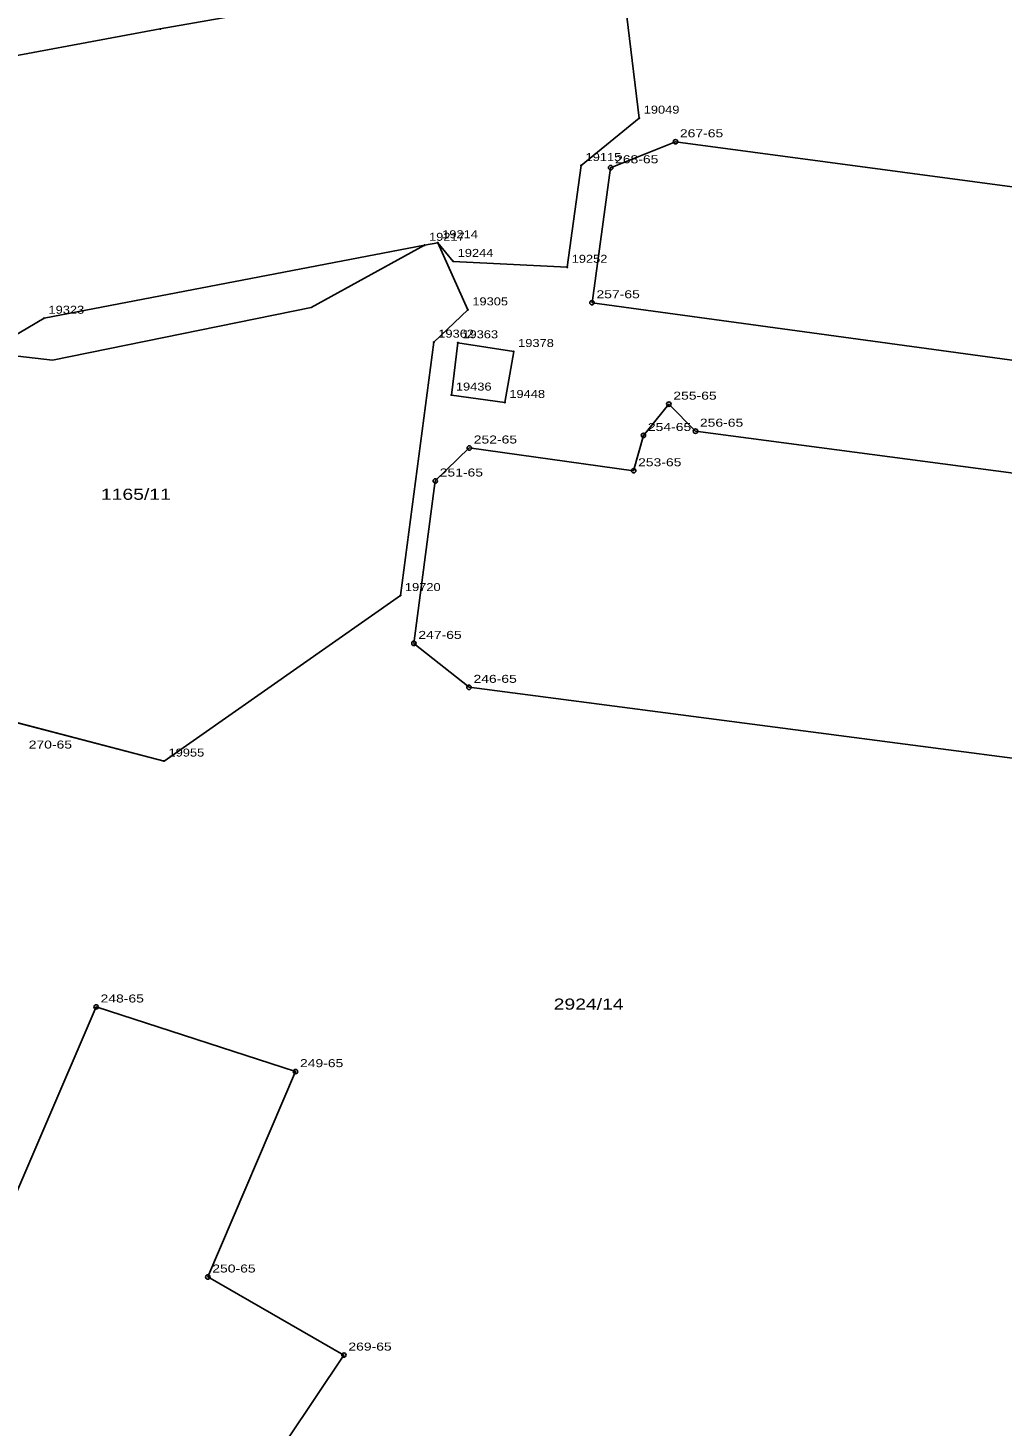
# Model space of a CAD drawing. Extents: x 4640203 to 4644676, y 5358265 to 5360852.
# Drawn here: x 4641831.5 to 4641941.1, y 5359260.5 to 5359417.7 of the extents above; entities that cross this region are included whole.
import ezdxf

# ---------------------------------------------------------------- set-up
doc = ezdxf.new("R2010")
doc.units = 0
doc.header["$LTSCALE"] = 0.36
doc.layers.add('24', color=7, linetype='Continuous')
for name, color, linetype, lineweight in [('25', 7, 'Continuous', 25), ('27', 7, 'Continuous', 25), ('8', 7, 'Continuous', 25)]:
    doc.layers.add(name, color=color, linetype=linetype, lineweight=lineweight)

msp = doc.modelspace()

# ---------------------------------------------------------------- linework, layer by layer
at = {"layer": '25'}
for points in [[(4641968.76, 5359437.03), (4641898.23, 5359424.32), (4641900.28, 5359407.6), (4641893.74, 5359402.27), (4641892.18, 5359390.83), (4641879.36, 5359391.49), (4641877.62, 5359393.59), (4641881.01, 5359386.04), (4641877.18, 5359382.41), (4641873.43, 5359353.92), (4641846.85, 5359335.31), (4641801.46, 5359347.14), (4641795.82, 5359358.1), (4641799.54, 5359361.64), (4641787.37, 5359370.51), (4641782.1, 5359375.41), (4641774.52, 5359383.26), (4641762.68, 5359395.51), (4641765.04, 5359405.61), (4641754.36, 5359405.58)], [(4641823.83, 5359413.44), (4641846.42, 5359417.62), (4641863.97, 5359420.72)], [(4641954.82, 5359378.65), (4641894.97, 5359386.84), (4641897.06, 5359402.02), (4641904.35, 5359404.94), (4641946.69, 5359399.26)], [(4641877.62, 5359393.59), (4641876.14, 5359393.3), (4641833.35, 5359385.1), (4641826.79, 5359381.23)], [(4641957.98, 5359333.57), (4641881.14, 5359343.6), (4641874.94, 5359348.54), (4641877.34, 5359366.8), (4641881.17, 5359370.51), (4641899.65, 5359367.95), (4641900.75, 5359371.92), (4641903.61, 5359375.44), (4641906.6, 5359372.4), (4641962.21, 5359365.06)], [(4641809.07, 5359237.5), (4641839.21, 5359307.66), (4641861.63, 5359300.39), (4641851.77, 5359277.3), (4641867.07, 5359268.52), (4641835.21, 5359220.92)]]:
    msp.add_lwpolyline(points, dxfattribs=at)
msp.add_lwpolyline([(4641879.16, 5359376.46), (4641885.17, 5359375.63), (4641886.16, 5359381.36), (4641879.89, 5359382.34)], close=True, dxfattribs=at)
at = {"layer": '27'}
for points in [[(4641898.01, 5359426.22), (4641898.23, 5359424.32), (4641900.28, 5359407.6), (4641893.74, 5359402.27), (4641892.18, 5359390.83), (4641879.36, 5359391.49), (4641877.62, 5359393.59), (4641881.01, 5359386.04), (4641877.18, 5359382.41), (4641873.43, 5359353.92), (4641846.85, 5359335.31), (4641832.29, 5359339.11), (4641801.46, 5359347.14), (4641795.82, 5359358.1), (4641799.54, 5359361.64), (4641787.37, 5359370.51), (4641782.1, 5359375.41), (4641774.52, 5359383.26), (4641762.68, 5359395.51), (4641765.04, 5359405.61), (4641765.73, 5359408.57)], [(4641823.83, 5359413.44), (4641846.42, 5359417.62), (4641863.97, 5359420.72)], [(4641954.82, 5359378.65), (4641894.97, 5359386.84), (4641897.06, 5359402.02), (4641904.35, 5359404.94), (4641946.69, 5359399.26)], [(4641877.62, 5359393.59), (4641876.14, 5359393.3), (4641863.39, 5359386.3), (4641834.3, 5359380.39), (4641826.79, 5359381.23)]]:
    msp.add_lwpolyline(points, dxfattribs=at)
msp.add_lwpolyline([(4641879.16, 5359376.46), (4641885.17, 5359375.63), (4641886.16, 5359381.36), (4641879.89, 5359382.34)], close=True, dxfattribs=at)
at = {"layer": '8'}
for centre, radius in [((4641846.42, 5359417.62), 0.045), ((4641900.28, 5359407.6), 0.045), ((4641904.35, 5359404.94), 0.25), ((4641893.74, 5359402.27), 0.045), ((4641897.06, 5359402.02), 0.25), ((4641876.14, 5359393.3), 0.045), ((4641877.62, 5359393.59), 0.045), ((4641879.36, 5359391.49), 0.045), ((4641892.18, 5359390.83), 0.045), ((4641881.01, 5359386.04), 0.045), ((4641894.97, 5359386.84), 0.25), ((4641833.35, 5359385.1), 0.045), ((4641877.18, 5359382.41), 0.045), ((4641879.89, 5359382.34), 0.045), ((4641886.16, 5359381.36), 0.045), ((4641879.16, 5359376.46), 0.045), ((4641885.17, 5359375.63), 0.045), ((4641903.61, 5359375.44), 0.25), ((4641900.75, 5359371.92), 0.25), ((4641906.6, 5359372.4), 0.25), ((4641881.17, 5359370.51), 0.25), ((4641877.34, 5359366.8), 0.25), ((4641899.65, 5359367.95), 0.25), ((4641873.43, 5359353.92), 0.045), ((4641874.94, 5359348.54), 0.25), ((4641881.14, 5359343.6), 0.25), ((4641846.85, 5359335.31), 0.045), ((4641839.21, 5359307.66), 0.25), ((4641861.63, 5359300.39), 0.25), ((4641851.77, 5359277.3), 0.25), ((4641867.07, 5359268.52), 0.25)]:
    msp.add_circle(centre, radius, dxfattribs=at)

# ---------------------------------------------------------------- texts
at = {"layer": '24', "width": 1.3}
for s, p in [('1165/11', (4641839.75, 5359364.68)), ('2924/14', (4641890.66, 5359307.35))]:
    msp.add_text(s, height=1.25, dxfattribs=at).set_placement(p)
at = {"layer": '8'}
for s, width, p in [('19049', 1.2, (4641900.78, 5359408.1)), ('267-65', 1.3, (4641904.85, 5359405.44)), ('19115', 1.2, (4641894.24, 5359402.77)), ('268-65', 1.3, (4641897.56, 5359402.52)), ('19217', 1.2, (4641876.64, 5359393.8)), ('19214', 1.2, (4641878.12, 5359394.09)), ('19244', 1.2, (4641879.86, 5359391.99)), ('19252', 1.2, (4641892.68, 5359391.33)), ('19305', 1.2, (4641881.51, 5359386.54)), ('257-65', 1.3, (4641895.47, 5359387.34)), ('19323', 1.2, (4641833.85, 5359385.6)), ('19362', 1.2, (4641877.68, 5359382.91)), ('19363', 1.2, (4641880.39, 5359382.84)), ('19378', 1.2, (4641886.66, 5359381.86)), ('19436', 1.2, (4641879.66, 5359376.96)), ('19448', 1.2, (4641885.67, 5359376.13)), ('255-65', 1.3, (4641904.11, 5359375.94)), ('254-65', 1.3, (4641901.25, 5359372.42)), ('256-65', 1.3, (4641907.1, 5359372.9)), ('252-65', 1.3, (4641881.67, 5359371.01)), ('253-65', 1.3, (4641900.15, 5359368.45)), ('251-65', 1.3, (4641877.84, 5359367.3)), ('19720', 1.2, (4641873.93, 5359354.42)), ('247-65', 1.3, (4641875.44, 5359349.04)), ('246-65', 1.3, (4641881.64, 5359344.1)), ('270-65', 1.3, (4641831.63, 5359336.71)), ('19955', 1.2, (4641847.35, 5359335.81)), ('248-65', 1.3, (4641839.71, 5359308.16)), ('249-65', 1.3, (4641862.13, 5359300.89)), ('250-65', 1.3, (4641852.27, 5359277.8)), ('269-65', 1.3, (4641867.57, 5359269.02))]:
    msp.add_text(s, height=0.9, dxfattribs=dict(at, width=width)).set_placement(p)

doc.saveas('drawing.dxf')
